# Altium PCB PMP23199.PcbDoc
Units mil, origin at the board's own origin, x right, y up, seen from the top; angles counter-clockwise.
Board outline 2600 x 2075 mil, 2 copper layers (Top Layer, Bottom Layer), stack 62 mil thick; 35 components, 17 nets, 75 pads, 7 vias.
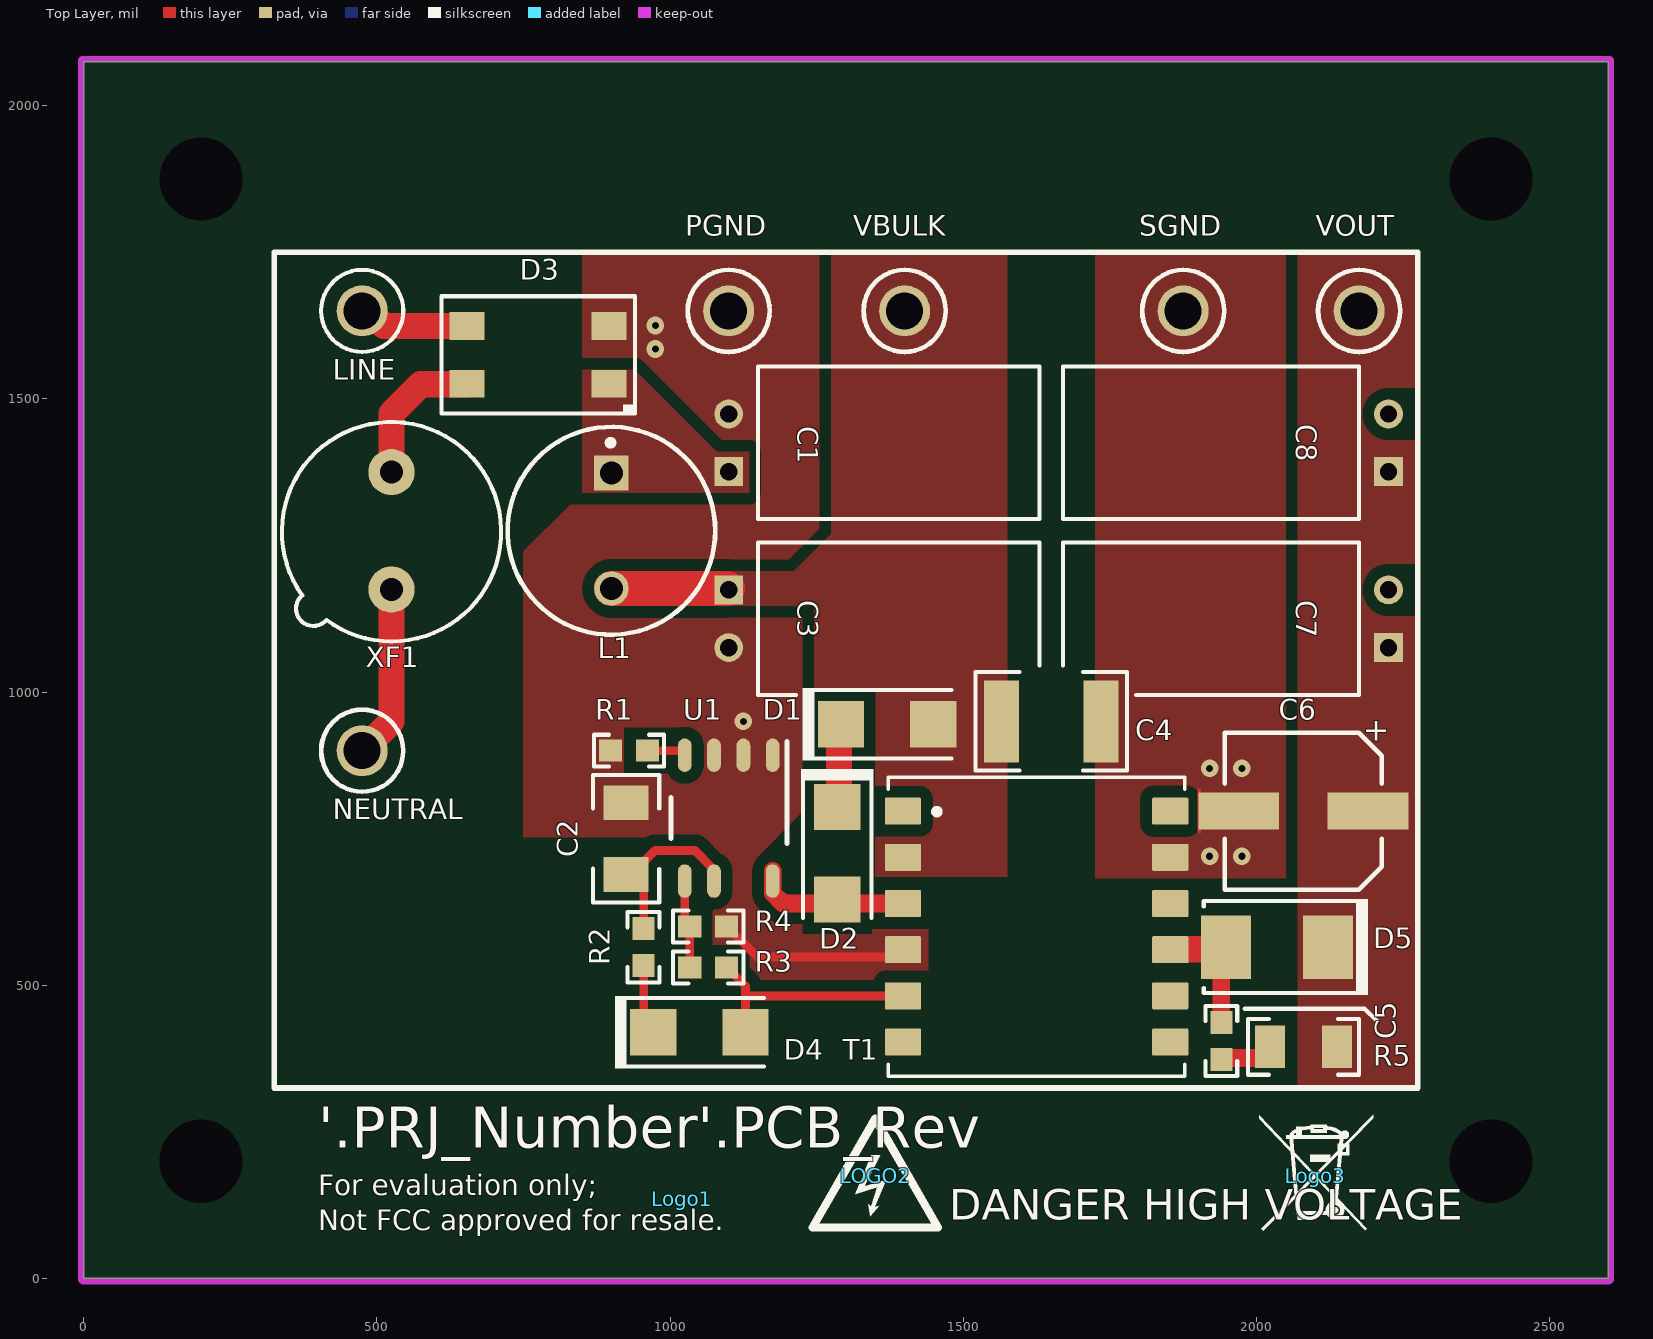
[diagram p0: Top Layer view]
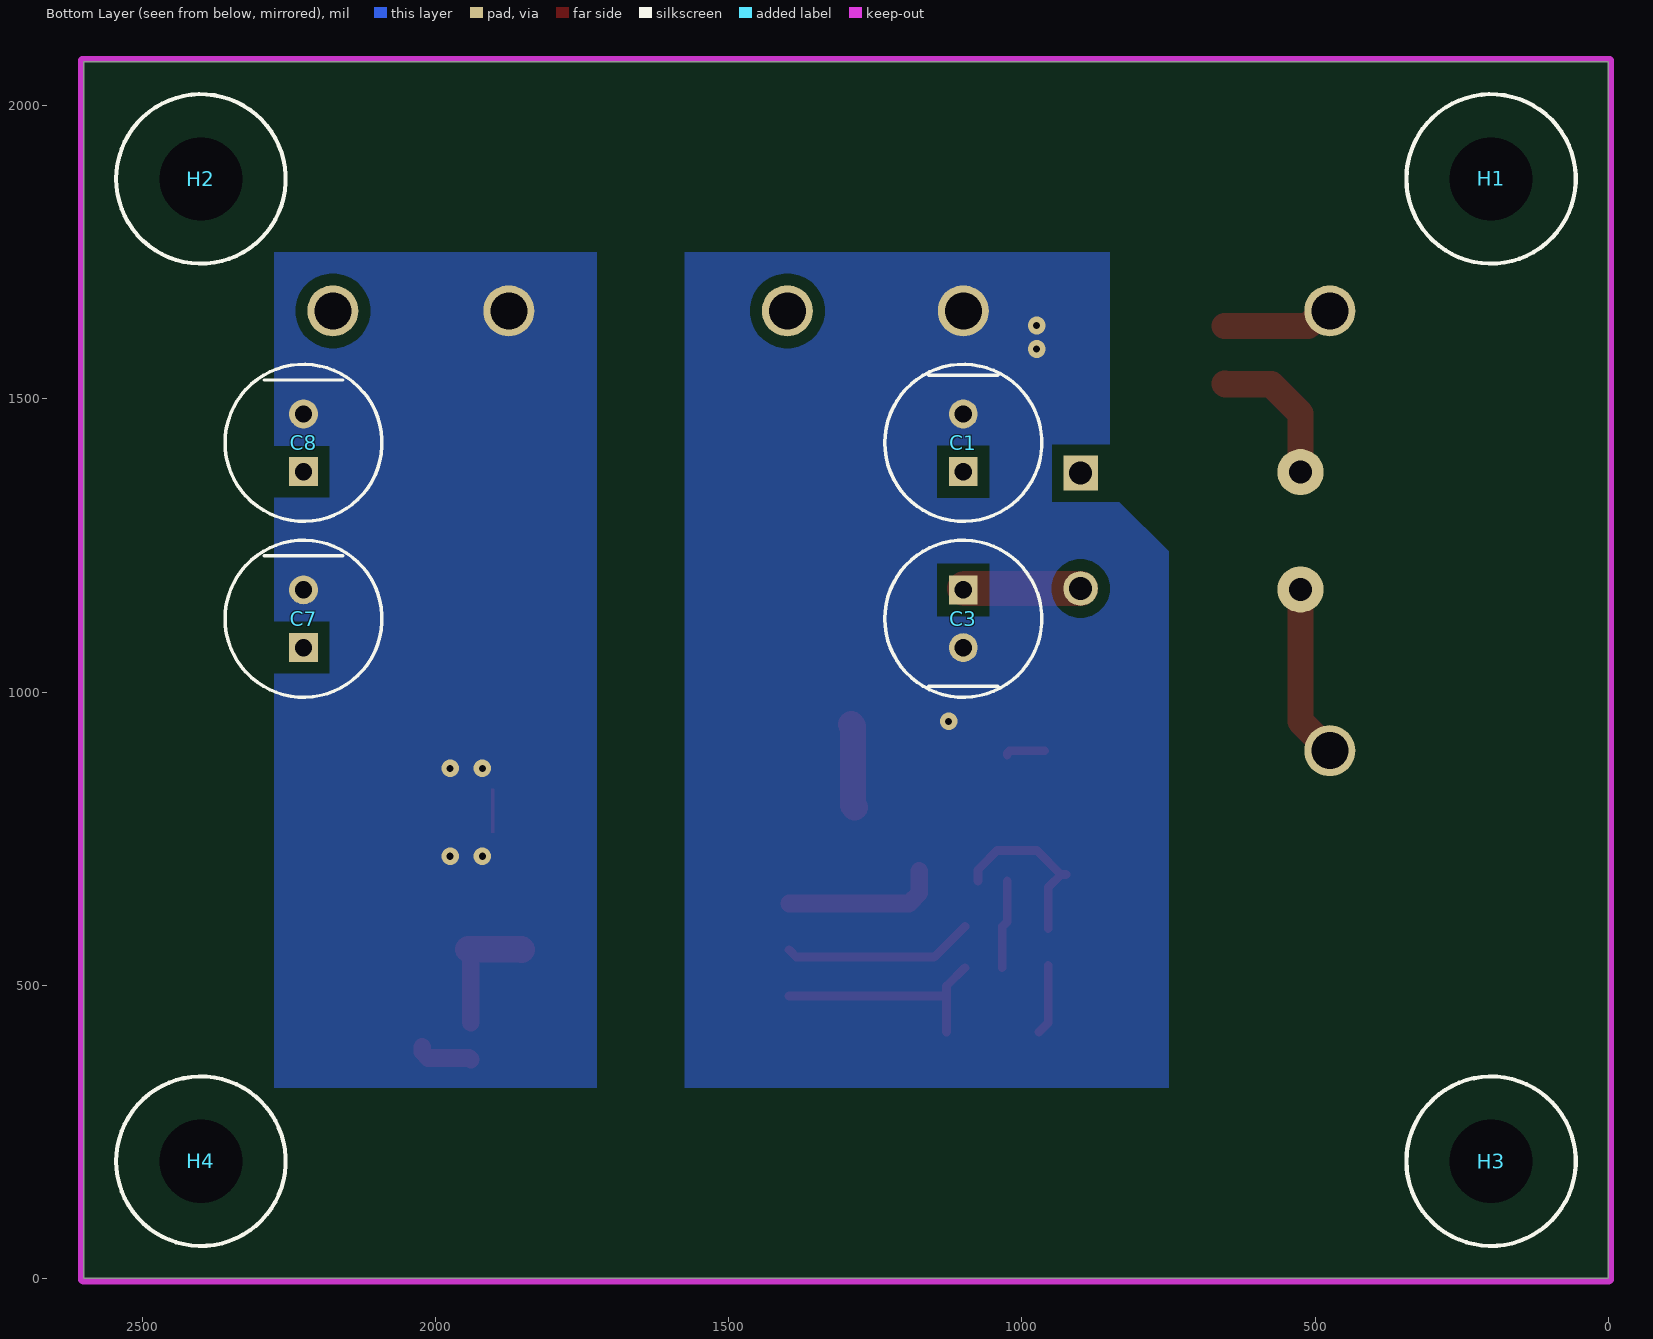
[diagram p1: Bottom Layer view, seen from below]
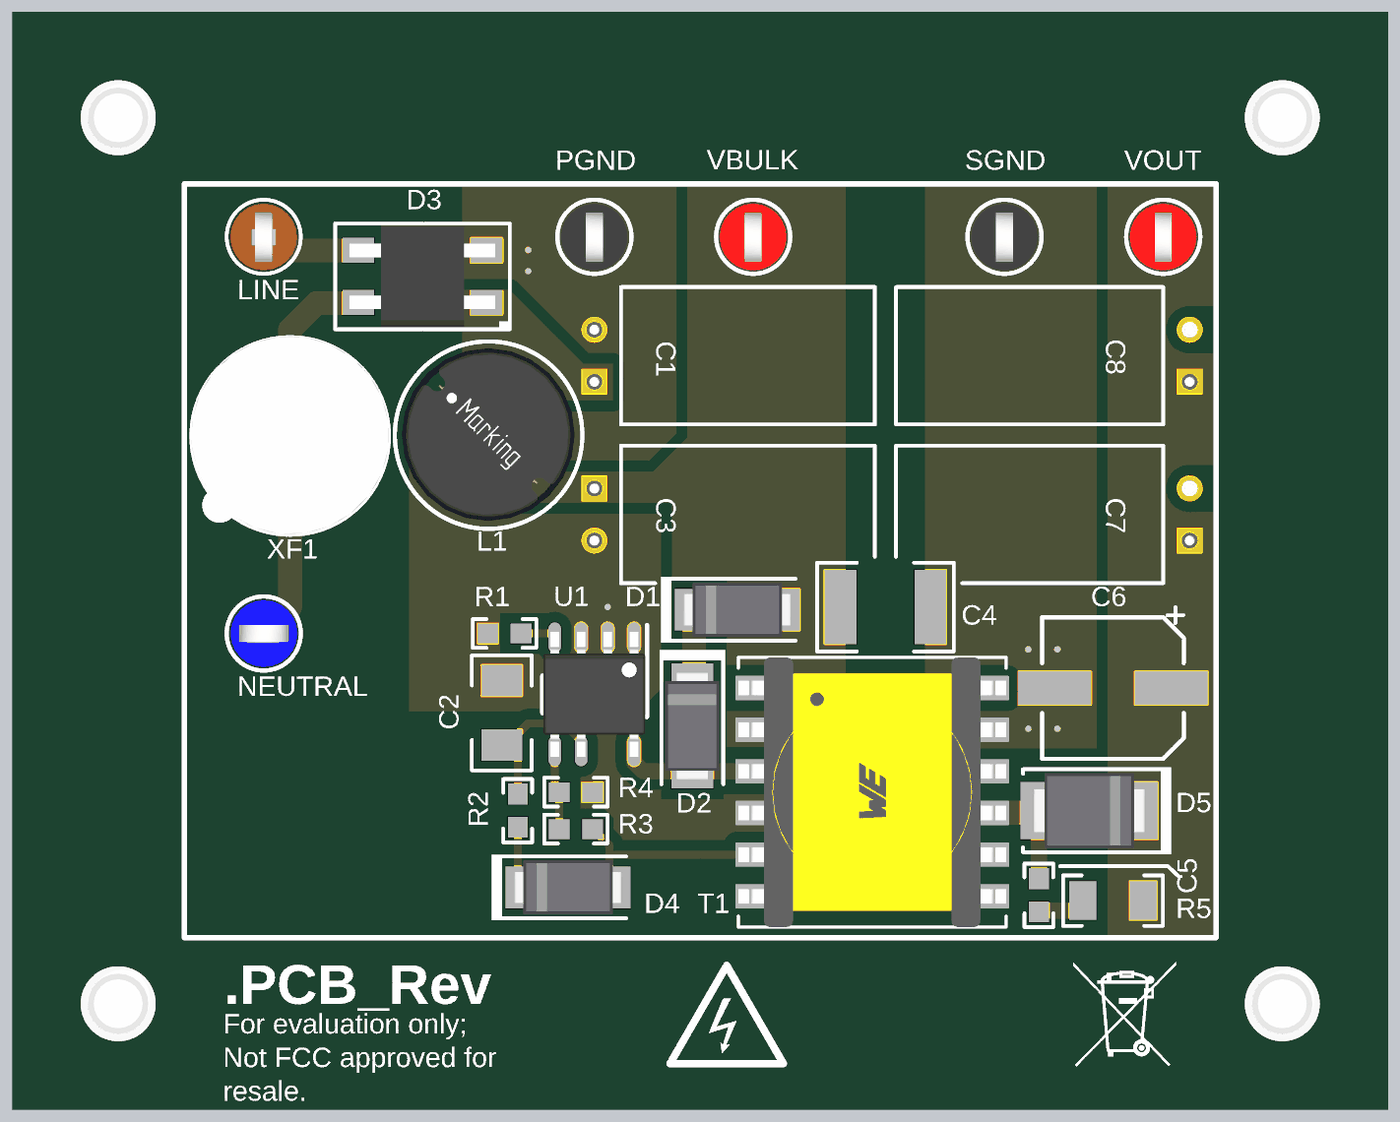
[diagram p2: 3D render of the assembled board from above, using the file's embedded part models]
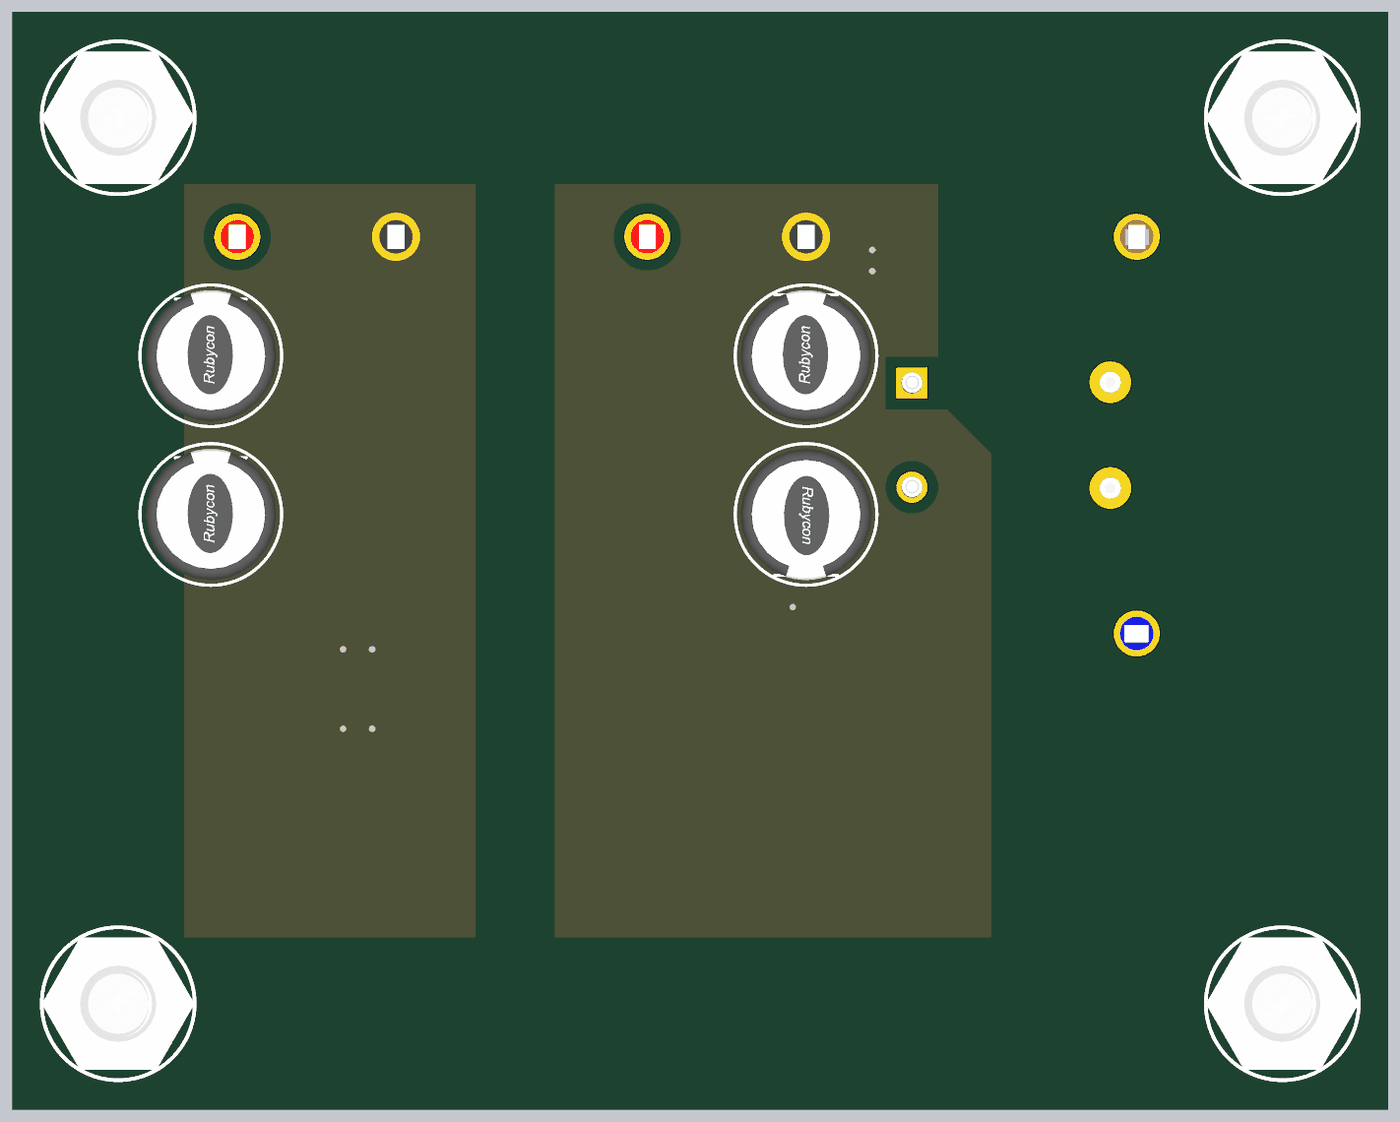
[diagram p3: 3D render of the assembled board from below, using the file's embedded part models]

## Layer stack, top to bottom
Top Solder: solder mask 0.4, Solder Resist, Dk 3.5
Top Layer: signal copper 1.4
Dielectric1: core 59.2, FR-4 High Tg, Dk 4.8
Bottom Layer: signal copper 1.4
Bottom Solder: solder mask 0.4, Solder Resist, Dk 3.5

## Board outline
0,0 0,2075 2600,2075 2600,0

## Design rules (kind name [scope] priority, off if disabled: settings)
AcuteAngle [All] p1: minimum=4.50000000000000E+0001 checktracksonly=FALSE
AssemblyTestPointUsage [All] p1: valid=2
BoardOutlineClearance BoardOutlineClearance_MountingHoles [OnCopper and InComponentClass('Mounting Holes')] p1: gap=25 ignorepadtopadclearanceinfootprint=FALSE
BoardOutlineClearance BoardOutlineClearance_Poly [OnCopper and InPoly] p2: gap=25 ignorepadtopadclearanceinfootprint=FALSE
BoardOutlineClearance [OnCopper and Not InComponentClass('Logo') and not InComponentClass('FiducialMark') and not InRegion(1000,500,4000,800)] p3: gap=25 ignorepadtopadclearanceinfootprint=FALSE
Clearance Clearance_2 [InNetClass('HV') vs Not InNetClass('HV')] p1: gap=60 ignorepadtopadclearanceinfootprint=FALSE
Clearance Clearance_1 [InNetClass('MV') vs Not InNetClass('MV')] p2: gap=30 ignorepadtopadclearanceinfootprint=FALSE
Clearance Clearance_Keepouts [((IsTrack Or IsArc) And Not InPoly) And IsFree and IsKeepOut vs ((IsTrack Or IsArc) And Not InPoly) And IsFree and IsKeepOut] p3: gap=0 ignorepadtopadclearanceinfootprint=FALSE
Clearance Clearance_BoardEdge_MountingHoles [OnCopper and InComponentClass('Mounting Holes') vs IsKeepOut] p4: gap=40 ignorepadtopadclearanceinfootprint=FALSE except(0: Arc-Hole Track-Hole SMDPad-Hole THPad-Hole Via-Hole Fill-Hole Poly-Hole Region-Hole Text-Hole)
Clearance Clearance_BoardEdge_Poly [OnCopper and InPoly vs IsKeepOut] p5: gap=50 ignorepadtopadclearanceinfootprint=FALSE except(0: Arc-Hole Track-Hole SMDPad-Hole THPad-Hole Via-Hole Fill-Hole Poly-Hole Region-Hole Text-Hole)
Clearance Clearance_BoardEdge [OnCopper and Not InComponentClass('Logo') and not InComponentClass('FiducialMark') and not InRegion(1000,500,4000,800) and Not IsKeepout vs IsKeepOut] p6: gap=50 ignorepadtopadclearanceinfootprint=FALSE
Clearance Clearance_Poly [InPolygon] p7: gap=20 ignorepadtopadclearanceinfootprint=FALSE except(0: Arc-Hole Track-Hole SMDPad-Hole THPad-Hole Via-Hole Fill-Hole Poly-Hole Region-Hole Text-Hole)
Clearance [All] p8: gap=7.87 ignorepadtopadclearanceinfootprint=FALSE except(0: Arc-Hole Track-Hole SMDPad-Hole THPad-Hole Via-Hole Fill-Hole Poly-Hole Region-Hole Text-Hole)
ComponentClearance ComponentClearance_MountingHoles_FiducialMarks [InComponentClass('Mounting Holes') vs InComponentClass('FiducialMark')] p1: gap=20 collisioncheckmode=3 verticalgap=10 showdistances=FALSE
ComponentClearance ComponentClearance_Shunt [InComponentClass('Header') vs InComponentClass('Shunt')] p2: gap=0 collisioncheckmode=3 verticalgap=0 showdistances=FALSE
ComponentClearance ComponentClearance_Logo [InComponentClass('Logo')] p3: gap=5 collisioncheckmode=3 verticalgap=10 showdistances=FALSE
ComponentClearance ComponentClearance_ScrewToNut [(HasFootprint('NY PMS 440 0025 PH')) vs (HasFootprint('Keystone_1902C'))] p4: gap=20 collisioncheckmode=3 verticalgap=100000 showdistances=FALSE
ComponentClearance ComponentClearance_MountingHoles [InComponentClass('Mounting Holes')] p5: gap=20 collisioncheckmode=3 verticalgap=10 showdistances=FALSE
ComponentClearance ComponentClearance_SmallPassives [HasFootprint('0201*') or HasFootprint('0402*') or HasFootprint('0508') or HasFootprint('0603*') or HasFootprint('0612') or HasFootprint('0805*') or HasFootprint('0815*') or HasFootprint('0830*') or HasFootprint('1206*') or HasFootprint('1210*') or HasFootprint('1808*') or HasFootprint('1812*') or HasFootprint('1825*') or HasFootprint('2010*') or HasFootprint('2220*') or HasFootprint('2225*') or HasFootprint('2512*') or HasFootprint('2728*') or HasFootprint('3518*') vs HasFootprint('0201*') or HasFootprint('0402*') or HasFootprint('0508') or HasFootprint('0603*') or HasFootprint('0612') or HasFootprint('0805*') or HasFootprint('0815*') or HasFootprint('0830*') or HasFootprint('1206*') or HasFootprint('1210*') or HasFootprint('1808*') or HasFootprint('1812*') or HasFootprint('1825*') or HasFootprint('2010*') or HasFootprint('2220*') or HasFootprint('2225*') or HasFootprint('2512*') or HasFootprint('2728*') or HasFootprint('3518*')] p6: gap=20 collisioncheckmode=3 verticalgap=20 showdistances=FALSE
ComponentClearance ComponentClearance_THtoSMT [IsThruComponent vs IsSMTComponent] p7: gap=10 collisioncheckmode=3 verticalgap=10 showdistances=FALSE
ComponentClearance ComponentClearance_THtoTH [IsThruComponent vs IsThruComponent] p8: gap=10 collisioncheckmode=3 verticalgap=10 showdistances=FALSE
ComponentClearance [All] p9: gap=10 collisioncheckmode=3 verticalgap=10 showdistances=FALSE
DiffPairsRouting [All] p1: maxlimit=100 minlimit=10 mostfreqgap=10 toplayer_minwidth=15 toplayer_maxwidth=15 toplayer_prefwidth=15 bottomlayer_minwidth=15 bottomlayer_maxwidth=15 bottomlayer_prefwidth=15 maxuncoupledlength=1000
FabricationTestPointUsage TestPointUsage [All] p1: valid=2 allowmultiple=FALSE
FabricationTestpoint Testpoint [All] p1: side=3 testpointundercomponent=TRUE minsize=40 maxsize=100 preferedsize=60 minholesize=0 maxholesize=40 preferedholesize=32 testpointgrid=1 allowsidetop=TRUE allowsidebottom=TRUE usegrid=TRUE gridtolerance=0.01
FanoutControl Fanout_LCC [IsLCC] p1: bgadir=Out bgaviamode=Centered fanoutstyle=Auto fanoutdirection=Alternating viagrid=1 // Fanout_LCC (Default Rule)
FanoutControl Fanout_BGA [IsBGA] p2: bgadir=Out bgaviamode=Centered fanoutstyle=Auto fanoutdirection=Alternating viagrid=1 // Fanout_BGA (Default Rule)
FanoutControl Fanout_Default [All] p4: bgadir=Out bgaviamode=Centered fanoutstyle=Auto fanoutdirection=Alternating viagrid=1 // Fanout_Default (Default Rule)
FanoutControl Fanout_Small [(CompPinCount < 5)] p5: bgadir=Out bgaviamode=Centered fanoutstyle=Auto fanoutdirection=OutThenIn viagrid=1 // Fanout_Small (Default Rule)
Height [All] p1: minheight=0 maxheight=3000 prefheight=500
HoleSize [All] p1: absolutevalues=TRUE maxlimit=251 minlimit=7.87 maxpercent=80.000 minpercent=20.000
MinimumAnnularRing MinimumAnnularRing_ThermalPadVias [IsVia and InAnyComponent] p1: minimumring=5.91
MinimumAnnularRing [All] p2: minimumring=8
MinimumSolderMaskSliver MinimumSolderMaskSliver_Logo [InComponentClass('Logo') vs InComponentClass('Logo')] p1: minsoldermaskwidth=0.7
MinimumSolderMaskSliver [All] p2: minsoldermaskwidth=3.94
PlaneConnect [All] p1: planeconnectstyle=Direct reliefexpansion=10 reliefentries=4 reliefconductorwidth=10 reliefairgap=10
PolygonConnect PolygonConnect_15 [All vs IsNamedPolygon('C109_2') Or  IsNamedPolygon('C107_2') Or  IsNamedPolygon('HV') Or  IsNamedPolygon('Q203_5') Or  IsNamedPolygon('C107_2') Or  IsNamedPolygon('HS') Or  IsNamedPolygon('Q201_5') Or  IsNamedPolygon('Q203_5') Or  IsNamedPolygon('C106_2') Or  IsNamedPolygon('C108_2') Or  IsNamedPolygon('Vout') Or  IsNamedPolygon('Q203_5') Or  IsNamedPolygon('C108_2') Or  IsNamedPolygon('C113_2') Or  IsNamedPolygon('Q203_5') Or  IsNamedPolygon('Q201_5') Or  IsNamedPolygon('C107_2') Or  IsNamedPolygon('C102_1') Or  IsNamedPolygon('SGND') Or  IsNamedPolygon('GND') Or  IsNamedPolygon('SGND') Or  IsNamedPolygon('GND') Or  IsNamedPolygon('IN+') Or  IsNamedPolygon('IN+') Or  IsNamedPolygon('Q201_5') Or  IsNamedPolygon('Q201_5') Or  IsNamedPolygon('SGND') Or  IsNamedPolygon('SGND') Or  IsNamedPolygon('Vout') Or  IsNamedPolygon('Vout') Or  IsNamedPolygon('IN+') Or  IsNamedPolygon('GND') Or  IsNamedPolygon('IN+') Or  IsNamedPolygon('GND')] p1: connectstyle=Direct reliefconductorwidth=10 reliefentries=4 polygonreliefangle="90 Angle" airgapwidth=10
PolygonConnect PolygonConnect_14 [All vs IsNamedPolygon('C106_2') Or  IsNamedPolygon('C107_2') Or  IsNamedPolygon('C107_2') Or  IsNamedPolygon('C107_2') Or  IsNamedPolygon('C102_1') Or  IsNamedPolygon('Q203_5') Or  IsNamedPolygon('Vout') Or  IsNamedPolygon('Q203_5') Or  IsNamedPolygon('Q203_5') Or  IsNamedPolygon('Q201_5') Or  IsNamedPolygon('C108_2') Or  IsNamedPolygon('Q203_5') Or  IsNamedPolygon('HS') Or  IsNamedPolygon('HV') Or  IsNamedPolygon('C108_2') Or  IsNamedPolygon('Q201_5') Or  IsNamedPolygon('C109_2') Or  IsNamedPolygon('Q201_5') Or  IsNamedPolygon('Q201_5') Or  IsNamedPolygon('C113_2')] p2: connectstyle=Direct reliefconductorwidth=10 reliefentries=4 polygonreliefangle="90 Angle" airgapwidth=10
PolygonConnect PolygonConnect_13 [All vs IsNamedPolygon('C102_1') Or  IsNamedPolygon('HV') Or  IsNamedPolygon('C107_2') Or  IsNamedPolygon('C109_2') Or  IsNamedPolygon('C107_2') Or  IsNamedPolygon('C108_2') Or  IsNamedPolygon('C106_2') Or  IsNamedPolygon('C108_2') Or  IsNamedPolygon('C113_2') Or  IsNamedPolygon('C107_2')] p3: connectstyle=Direct reliefconductorwidth=10 reliefentries=4 polygonreliefangle="90 Angle" airgapwidth=10
PolygonConnect PolygonConnect_12 [All vs IsNamedPolygon('C107_2') Or  IsNamedPolygon('C113_2') Or  IsNamedPolygon('C106_2') Or  IsNamedPolygon('C107_2') Or  IsNamedPolygon('C107_2') Or  IsNamedPolygon('C102_1')] p4: connectstyle=Direct reliefconductorwidth=10 reliefentries=4 polygonreliefangle="90 Angle" airgapwidth=10
PolygonConnect PolygonConnect_11 [All vs IsNamedPolygon('C106_2') Or  IsNamedPolygon('C102_1') Or  IsNamedPolygon('C107_2') Or  IsNamedPolygon('C107_2') Or  IsNamedPolygon('C107_2')] p5: connectstyle=Direct reliefconductorwidth=10 reliefentries=4 polygonreliefangle="90 Angle" airgapwidth=10
PolygonConnect PolygonConnect_10 [All vs IsNamedPolygon('C106_2')] p6: connectstyle=Direct reliefconductorwidth=10 reliefentries=4 polygonreliefangle="90 Angle" airgapwidth=10
PolygonConnect PolygonConnect_9 [All vs IsNamedPolygon('C11_1') Or  IsNamedPolygon('Vin') Or  IsNamedPolygon('Vin') Or  IsNamedPolygon('5V') Or  IsNamedPolygon('D6_2') Or  IsNamedPolygon('Q3_3') Or  IsNamedPolygon('GND2') Or  IsNamedPolygon('GND2') Or  IsNamedPolygon('GND') Or  IsNamedPolygon('Q3_4') Or  IsNamedPolygon('12V5') Or  IsNamedPolygon('GND') Or  IsNamedPolygon('12V5') Or  IsNamedPolygon('D3_1')] p7: connectstyle=Direct reliefconductorwidth=10 reliefentries=4 polygonreliefangle="90 Angle" airgapwidth=10
PolygonConnect PolygonConnect_8 [All vs IsNamedPolygon('C11_1') Or  IsNamedPolygon('Vin') Or  IsNamedPolygon('12V5') Or  IsNamedPolygon('Q3_3') Or  IsNamedPolygon('GND2') Or  IsNamedPolygon('GND2') Or  IsNamedPolygon('5V') Or  IsNamedPolygon('Q3_4') Or  IsNamedPolygon('12V5')] p8: connectstyle=Direct reliefconductorwidth=10 reliefentries=4 polygonreliefangle="90 Angle" airgapwidth=10
PolygonConnect PolygonConnect_7 [All vs IsNamedPolygon('GND2') Or  IsNamedPolygon('GND2') Or  IsNamedPolygon('5V') Or  IsNamedPolygon('12V5') Or  IsNamedPolygon('12V5') Or  IsNamedPolygon('C11_1')] p9: connectstyle=Direct reliefconductorwidth=10 reliefentries=4 polygonreliefangle="90 Angle" airgapwidth=10
PolygonConnect PolygonConnect_6 [All vs IsNamedPolygon('GND2') Or  IsNamedPolygon('SGND') Or  IsNamedPolygon('GND1') Or  IsNamedPolygon('C901_1') Or  IsNamedPolygon('SGND') Or  IsNamedPolygon('GND2') Or  IsNamedPolygon('GND1')] p10: connectstyle=Direct reliefconductorwidth=10 reliefentries=4 polygonreliefangle="90 Angle" airgapwidth=10
PolygonConnect PolygonConnect_5 [All vs IsNamedPolygon('GND1') Or  IsNamedPolygon('GND1')] p11: connectstyle=Direct reliefconductorwidth=10 reliefentries=4 polygonreliefangle="90 Angle" airgapwidth=10
PolygonConnect PolygonConnect_4 [All vs IsNamedPolygon('C21_1') Or  IsNamedPolygon('C5_1') Or  IsNamedPolygon('C12_2') Or  IsNamedPolygon('C2_2') Or  IsNamedPolygon('C13_1') Or  IsNamedPolygon('C28_1') Or  IsNamedPolygon('C6_1') Or  IsNamedPolygon('GND') Or  IsNamedPolygon('GND2') Or  IsNamedPolygon('C14_1') Or  IsNamedPolygon('C13_1') Or  IsNamedPolygon('Q1_3') Or  IsNamedPolygon('C14_1') Or  IsNamedPolygon('C5_1') Or  IsNamedPolygon('GND2') Or  IsNamedPolygon('C28_1') Or  IsNamedPolygon('D5_2') Or  IsNamedPolygon('D6_2') Or  IsNamedPolygon('D2_1') Or  IsNamedPolygon('C12_2') Or  IsNamedPolygon('D2_1') Or  IsNamedPolygon('C4_1') Or  IsNamedPolygon('C4_1') Or  IsNamedPolygon('C2_2') Or  IsNamedPolygon('GND') Or  IsNamedPolygon('C33_1') Or  IsNamedPolygon('C9_1')] p12: connectstyle=Direct reliefconductorwidth=10 reliefentries=4 polygonreliefangle="90 Angle" airgapwidth=10
PolygonConnect PolygonConnect_3 [All vs IsNamedPolygon('C28_1') Or  IsNamedPolygon('C12_2') Or  IsNamedPolygon('C28_1') Or  IsNamedPolygon('C9_1') Or  IsNamedPolygon('D5_2') Or  IsNamedPolygon('C12_2') Or  IsNamedPolygon('C2_2') Or  IsNamedPolygon('C14_1') Or  IsNamedPolygon('C4_1') Or  IsNamedPolygon('C14_1') Or  IsNamedPolygon('D6_2') Or  IsNamedPolygon('GND2') Or  IsNamedPolygon('Q1_3') Or  IsNamedPolygon('C5_1') Or  IsNamedPolygon('D2_1') Or  IsNamedPolygon('C4_1') Or  IsNamedPolygon('C13_1') Or  IsNamedPolygon('C5_1') Or  IsNamedPolygon('C13_1') Or  IsNamedPolygon('C33_1') Or  IsNamedPolygon('D2_1') Or  IsNamedPolygon('GND') Or  IsNamedPolygon('GND') Or  IsNamedPolygon('GND2') Or  IsNamedPolygon('C2_2') Or  IsNamedPolygon('C6_1') Or  IsNamedPolygon('C21_1')] p13: connectstyle=Direct reliefconductorwidth=10 reliefentries=4 polygonreliefangle="90 Angle" airgapwidth=10
PolygonConnect PolygonConnect_2 [All vs IsNamedPolygon('C21_1') Or  IsNamedPolygon('C4_1') Or  IsNamedPolygon('D5_2') Or  IsNamedPolygon('C5_1') Or  IsNamedPolygon('C14_1') Or  IsNamedPolygon('C13_1') Or  IsNamedPolygon('C4_1') Or  IsNamedPolygon('C33_1') Or  IsNamedPolygon('C12_2') Or  IsNamedPolygon('D2_1') Or  IsNamedPolygon('C2_2') Or  IsNamedPolygon('C28_1') Or  IsNamedPolygon('C12_2') Or  IsNamedPolygon('D2_1') Or  IsNamedPolygon('C5_1') Or  IsNamedPolygon('Q1_3') Or  IsNamedPolygon('GND') Or  IsNamedPolygon('D6_2') Or  IsNamedPolygon('C6_1') Or  IsNamedPolygon('C2_2') Or  IsNamedPolygon('C14_1') Or  IsNamedPolygon('C28_1') Or  IsNamedPolygon('C13_1') Or  IsNamedPolygon('C9_1') Or  IsNamedPolygon('GND')] p14: connectstyle=Direct reliefconductorwidth=10 reliefentries=4 polygonreliefangle="90 Angle" airgapwidth=10
PolygonConnect PolygonConnect_1 [All vs IsNamedPolygon('C28_1') Or  IsNamedPolygon('D5_2') Or  IsNamedPolygon('C5_1') Or  IsNamedPolygon('C5_1') Or  IsNamedPolygon('D2_1') Or  IsNamedPolygon('C21_1') Or  IsNamedPolygon('C9_1') Or  IsNamedPolygon('C4_1') Or  IsNamedPolygon('C14_1') Or  IsNamedPolygon('C28_1') Or  IsNamedPolygon('C6_1') Or  IsNamedPolygon('C12_2') Or  IsNamedPolygon('C33_1') Or  IsNamedPolygon('C4_1') Or  IsNamedPolygon('C13_1') Or  IsNamedPolygon('C12_2') Or  IsNamedPolygon('D6_2') Or  IsNamedPolygon('C2_2') Or  IsNamedPolygon('C14_1') Or  IsNamedPolygon('D2_1') Or  IsNamedPolygon('C2_2') Or  IsNamedPolygon('C13_1')] p15: connectstyle=Direct reliefconductorwidth=10 reliefentries=4 polygonreliefangle="90 Angle" airgapwidth=10
PolygonConnect [All] p16: connectstyle=Direct reliefconductorwidth=10 reliefentries=4 polygonreliefangle="90 Angle" airgapwidth=10
RoutingVias ThermalPadVias [IsVia and InAnyComponent] p1: holewidth=7.87 width=19.68 viastyle="Through Hole" minholewidth=7.87 minwidth=19.68 maxholewidth=12.99 maxwidth=23.62
RoutingVias [All] p2: holewidth=16 width=34 viastyle="Through Hole" minholewidth=7.87 minwidth=20 maxholewidth=40 maxwidth=65
SilkToBoardRegionClearance [Not ((IsComment or IsDesignator) And (Hide <> 'False')) and not InRegion(1000,500,4000,800)] p1:
SilkToSilkClearance SilkToSilkClearance_Pb-FreeLogo [(HasFootprint('Pb-Free_Overlay_Medium') OR HasFootprint('Pb-Free_Overlay_Small')) vs (HasFootprint('Pb-Free_Overlay_Medium') OR HasFootprint('Pb-Free_Overlay_Small'))] p1: silktosilkclearance=0
SilkToSilkClearance [All] p2: silktosilkclearance=4
SilkToSolderMaskClearance SilkToComponentPadClearance [IsPad and InAnycomponent] p1: minsilkscreentomaskgap=5 clearancetoexposedcopper=TRUE
SilkToSolderMaskClearance "Silk to Solder Mask Opening" [All] p2: minsilkscreentomaskgap=4 clearancetoexposedcopper=FALSE
SolderMaskExpansion [All] p1: expansion=1.97 istentingtop=FALSE
Width [All] p1: maxlimit=100 minlimit=6 preferedwidth=10 checkconnectedcopper=TRUE
14 further rules are at their usual default settings.

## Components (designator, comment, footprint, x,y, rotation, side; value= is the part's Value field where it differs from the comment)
C1 "250PX2R2MEFC6.3X11" FP-250PX2R2MEFC6.3X11_RADIAL-MFG 1100,1425 r270 bottom value=2.2µF
C2 "GRM31CR71E106KA12L" 1206_180M 925,750 r90 top value=10uF
C3 "250PX2R2MEFC6.3X11" FP-250PX2R2MEFC6.3X11_RADIAL-MFG 1100,1125 r90 bottom value=2.2µF
C4 "C4532X7R3D222K130KA" 1812_HV 1650,950 r180 top value=2200pF
C5 "GRM188R71H471KA01D" 0603 1940,405 r90 top value=470pF
C6 "875105344009" WCAP-PSLP_630x580 2080,796.85 r180 top value=82uF
C7 "6.3ZLH470MEFC6.3X11" FP-6.3ZLH470MEFC6.3X11_RADIAL-MFG 2225,1125 r270 bottom value=470µF
C8 "6.3ZLH470MEFC6.3X11" FP-6.3ZLH470MEFC6.3X11_RADIAL-MFG 2225,1425 r270 bottom value=470µF
D1 "SMAJ170A" SMA 1370,945 r0 top value=170V
D2 "US1G-13-F" SMA 1285,725 r270 top value=400V
D3 "RH06-T" MiniDIP 775,1575 r180 top value=600V
D4 "US1B-13-F" SMA 1050,420 r0 top value=100V
D5 "B160B-13-F" SMB 2035,565 r180 top value=60V
H1 "4820" KEYSTONE_4820 200,1875 r180 bottom
H2 "4820" KEYSTONE_4820 2400,1875 r180 bottom
H3 "4820" KEYSTONE_4820 200,200 r180 bottom
H4 "4820" KEYSTONE_4820 2400,200 r180 bottom
L1 "744741101" WE-TI_8055 900,1275 r270 top value=100uH
LINE "5125" Keystone5125 475,1650 r0 top
Logo1 "FCC disclaimer" FCC_disclaimer 1020,135 r0 top
LOGO2 "DANGER HIGH VOLTAGE" IEC_HighVoltage_Small 1350,175 r0 top
Logo3 "WEEE logo" WEEE_Minimum 2100,175 r0 top
NEUTRAL "5127" Keystone5127 475,900 r90 top
PGND "5011" Keystone5011 1100,1650 r0 top
R1 "CRCW06033K01FKEA" 0603 930,900 r0 top value=3.01k
R2 "CRCW060310R0JNEA" 0603 955,565 r90 top value=10
R3 "CRCW060395K3FKEA" 0603 1065,530 r0 top value=95.3k
R4 "CRCW060332K4FKEA" 0603 1065,600 r180 top value=32.4k
R5 "CRCW120610K0JNEA" 1206 2080,395 r0 top value=10k
SGND "5011" Keystone5011 1875,1650 r0 top
T1 "750319943" FP-750319943_SMT12_12MM85_12MM95-MFG 1625,600 r0 top
U1 "UCC28911DR" D0007A_N 1100,785 r270 top
VBULK "5010" Keystone5010 1400,1650 r0 top
VOUT "5010" Keystone5010 2175,1650 r0 top
XF1 "56000001009" FuseHolder_560000010 525,1275 r270 top value=TR5

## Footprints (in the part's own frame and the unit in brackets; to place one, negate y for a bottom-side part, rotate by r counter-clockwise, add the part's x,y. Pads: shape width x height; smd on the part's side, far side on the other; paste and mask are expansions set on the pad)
0603 [mm] "0603 from SM-752 data"
  rect 1x0.95 smd: 1(-0.8,0) 2(0.8,0)
  silkscreen extent -1.52,-0.69 1.52,0.69, body extent -0.87,-0.47 0.87,0.47, height 1
1206 [mm] "1206 from SM-752 data"
  rect 1.3x1.85 smd: 1(-1.45,0) 2(1.45,0)
  silkscreen extent -2.4,-1.21 2.4,1.21, body extent -1.7,-0.9 1.7,0.9, height 1.35
1206_180M [mm] "1206_180"
  rect 1.5x1.95 smd: 1(-1.55,0) 2(1.55,0)
  silkscreen extent -2.76,-1.44 2.76,1.44, body extent -1.75,-0.95 1.75,0.95, height 1.8
1812_HV [mil] "PRG recommended land pattern"
  rect 60x140 smd: 1(-85,0) 2(85,0)
  silkscreen extent -129,-84 129,84, body extent -94,-67 94,67, height 53
D0007A_N [mm] "SOIC, 7-Leads, Body 4.9x3.9mm, Pitch 1.27mm, IPC Medium Density"
  oval 1.45x0.6 smd: 1(-2.725,1.905) 2(-2.725,0.635) 3(-2.725,-0.635) 4(-2.725,-1.905) 5(2.725,-1.905) 6(2.725,-0.635) 8(2.725,1.905)
  silkscreen extent -3.32,-2.5 1.1,2.52, body extent -3.01,-2.45 3.01,2.45, height 1.75
FCC_disclaimer [mil]
FP-6.3ZLH470MEFC6.3X11_RADIAL-MFG [mm]
  round 1.25 hole 0.75 paste-1000 mask+0: 1(-1.25,0)
  rect 1.25x1.25 hole 0.75 paste-1000 mask+0: 2(1.25,0)
  silkscreen extent -3.4,-3.4 3.4,3.4, body extent -3.15,-3.15 3.15,3.15, height 12.5
FP-250PX2R2MEFC6.3X11_RADIAL-MFG [mm]
  round 1.25 hole 0.75 paste-1000 mask+0: 1(-1.25,0)
  rect 1.25x1.25 hole 0.75 paste-1000 mask+0: 2(1.25,0)
  silkscreen extent -3.4,-3.4 3.4,3.4, body extent -3.15,-3.15 3.15,3.15, height 13
FP-750319943_SMT12_12MM85_12MM95-MFG [mm]
  rrect9% 1.57x1.17 smd paste+0 mask+0: 1(-5.79,5) 2(-5.79,3) 3(-5.79,1) 4(-5.79,-1) 5(-5.79,-3) 6(-5.79,-5) 7(5.79,-5) 8(5.79,-3) 9(5.79,-1) 10(5.79,1) 11(5.79,3) 12(5.79,5)
  silkscreen extent -6.43,-6.48 6.43,6.48, body extent -6.68,-6.58 6.68,6.58, height 0.25
FuseHolder_560000010 [mm] "Littelfuse fuse holder TR5"
  round 2 hole 1: 1(-2.54,0) 2(2.54,0)
  silkscreen extent -4.71,-4.75 4.79,4.75, body extent -4.75,-4.74 4.75,4.75, height 5.6
IEC_HighVoltage_Small [mil]
  silkscreen extent -107,-88 107,97
Keystone5010 [mil] "Keystone Multipurpose loops"
  round 87 hole 63: 1(0,0)
  silkscreen extent -70,-70 70,70, body extent -63,-63 63,62, height 319
Keystone5011 [mil] "Keystone Multipurpose loops"
  round 87 hole 63: 1(0,0)
  silkscreen extent -70,-70 70,70, body extent -63,-63 63,62, height 319
Keystone5125 [mil] "Keystone Multipurpose loops"
  round 87 hole 63: 1(0,0)
  silkscreen extent -70,-70 70,70, body extent -63,-63 63,62, height 319
Keystone5127 [mil] "Keystone Multipurpose loops"
  round 87 hole 63: 1(0,0)
  silkscreen extent -70,-70 70,70, body extent -63,-63 63,62, height 319
KEYSTONE_4820 [mm] "HEX NYLON STANDOFF 6-32, M-F 1\""
  round 0.025 on Mech4: 0(0,0)
  round 1 hole 3.6 unplated: MH(0,0)
  silkscreen extent -3.67,-3.67 3.67,3.67, body extent -3.67,-3.17 3.67,3.18, height 25.42
MiniDIP [mm] "Land pattern created based on STEP model."
  rect 1.52x1.2 smd: 1(-3.075,1.25) 2(-3.075,-1.25) 3(3.075,-1.25) 4(3.075,1.25)
  silkscreen extent -4.19,-2.54 4.19,2.54, body extent -3.5,-2.45 3.5,2.45, height 2.75
SMA [mm] "Molded Diode, 2-Leads, Body 4.3x2.6mm, IPC Medium Density, based on OnSemi component dimensions and land pattern"
  rect 2x2 smd: 1(-2,0) 2(2,0)
  silkscreen extent -3.66,-1.57 2.79,1.57, body extent -2.6,-1.3 2.6,1.3, height 2.42
SMB [mil] "Molded Diode, 2-Leads, Body 5.4x3.6mm, IPC Medium Density, based on OnSemi component dimensions"
  rect 85x107.99 smd: 1(-87.01,0) 2(87.01,0)
  silkscreen extent -155,-82 125,82, body extent -106,-71 106,71, height 91
WCAP-PSLP_630x580 [mm] "SMD, 2-Leads, Dia 6.3mm"
  rect 3.5x1.6 smd: 1(-2.8,0) 2(2.8,0)
  silkscreen extent -3.4,-3.4 3.4,3.4, body extent -3.4,-3.4 3.4,3.4, height 5.81
WE-TI_8055 [mm] "Wurth"
  rect 1.5x1.5 hole 1: 1(-2.5,0)
  round 1.5 hole 1: 2(2.5,0)
  silkscreen extent -4.5,-4.5 4.5,4.5, body extent -5.89,-5.88 5.81,5.83, height 5.51
WEEE_Minimum [mil] "WEEElie bin"
  silkscreen extent -95,-94 99,104

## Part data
C1 C3: library part CMP-0094367-1, "2.2 µF 250 V Aluminum Electrolytic Capacitors Radial, Can - 1000 Hrs @ 105°C", Digikey Part Number=1189-1207-ND, Leakage Current=55uA, Manufacturer=Rubycon, Mouser Part Number=232-250PX2R2MEFC63X1, Operating Temperature Range="-40°C to +105°C", Tolerance_%=20%, ValueDisplayed=2.2uF
C2: library part CMP-0008965-2, "CAP, CERM, 10 uF, 25 V, +/- 10%, X7R, 1206", Cap_Case=2220, Manufacturer=MuRata, Supplier Part Number 1=81-GRM31CR71E106KA12, TempCo=X7R, Tolerance_%=10%, Value1=Unknown, Value2=25V, ValueDisplayed=10uF
C4: library part CMP-0009358-2, "CAP, CERM, 2200 pF, 2000 V, +/- 10%, X7R, 1812", Cap_Case=1812, Manufacturer=TDK, Supplier Part Number 1=445-2389-1-ND, TempCo=X7R, Tolerance_%=10%, Value1=Unknown, Value2=2000V, ValueDisplayed=2200pF
C5: library part CMP-0007455-4, "CAP, CERM, 470 pF, 50 V, +/- 10%, X7R, 0603", Cap_Case=0603, Manufacturer=MuRata, Supplier Part Number 1=490-1489-1-ND, TempCo=X7R, Tolerance_%=10%, Value1=Unknown, Value2=50V, ValueDisplayed=470pF
C6: library part CMP-0012165-3, "CAP, Aluminum Polymer, 82 uF, 16 V, +/- 20%, 0.03 ohm, D6.3xL5.8mm SMD", Cap_Case=6.3x5.8mm, Manufacturer="Wurth Elektronik", Supplier Part Number 1=732-6424-1-ND, Tolerance_%=20%, Value1="0.03 ohm", Value2=16V, ValueDisplayed=82uF
C7 C8: library part CMP-0094403-1, "470 µF 6.3 V Aluminum Electrolytic Capacitors Radial, Can - 6000 Hrs @ 105°C", Digikey Part Number=1189-1769-ND, Leakage Current=29.61uA, Manufacturer=Rubycon, Mouser Part Number=232-63ZLH470MEFC63X1, Operating Temperature Range="-40°C to +105°C", Tolerance_%=20%, ValueDisplayed=470uF
D1: library part CMP-0084984-1, "Diode, TVS, Uni, 170 V, 275 Vc, 400 W, 1.5 A, SMA", Manufacturer=Littelfuse, Value1=275V
D2: library part CMP-0077026-2, "Diode, Ultrafast, 400 V, 1 A, SMA", Manufacturer="Diodes Inc.", Value1=1A, Value2=1.3V
D3: library part CMP-0029221-3, "Diode, Switching-Bridge, 600 V, 0.5 A, MiniDIP", Manufacturer="Diodes Inc.", Value1=0.5A, Value2=1.15V
D4: library part CMP-0076888-2, "Diode, Ultrafast, 100 V, 1 A, SMA", Manufacturer="Diodes Inc.", Value1=1A, Value2=1V
D5: library part CMP-0028390-2, "Diode, Schottky, 60 V, 1 A, SMB", Manufacturer="Diodes Inc.", Value1=1A, Value2=0.7V
H1 H2 H3 H4: library part CMP-0003652-1, Manufacturer=Keystone, Supplier Part Number 1=36-4820-ND
L1: library part CMP-0064515-2, "Inductor, Wirewound, Ferrite, 100 uH, 1.1 A, 0.39 ohm, TH", Manufacturer="Wurth Elektronik", Supplier Part Number 1=732-3729-ND, Value1="0.39 ohm", Value2=1.1A, ValueDisplayed=100uH
LINE: library part CMP-0055157-1, "Test Point, Multipurpose, Brown, TH", Color=Brown, Manufacturer=Keystone, Supplier Part Number 1=36-5125-ND
Logo1: library part CMP-0074847-1, "FCC_disclaimer"
LOGO2: library part CMP-0074835-1, "IEC 61010-1 High Voltage Warning"
Logo3: library part CMP-0074769-1
NEUTRAL: library part CMP-0055156-1, "Test Point, Multipurpose, Blue, TH", Color=Blue, Manufacturer=Keystone, Supplier Part Number 1=36-5127-ND
PGND SGND: library part CMP-0055148-1, "Test Point, Multipurpose, Black, TH", Color=Black, Manufacturer=Keystone, Supplier Part Number 1=36-5011-ND
R1: library part CMP-0022371-4, "RES, 3.01 k, 1%, 0.1 W, AEC-Q200 Grade 0, 0603", Manufacturer=Vishay-Dale, Power_W=100mW, Supplier Part Number 1=541-3.01KHCT-ND, TempCo="100 ppm/C", Tolerance_%=1%, Value2=0.1W, Value_Code=3k01, ValueDisplayed=3.01k
R2: library part CMP-0025703-4, "RES, 10, 5%, 0.1 W, AEC-Q200 Grade 0, 0603", Manufacturer=Vishay-Dale, Power_W=100mW, Supplier Part Number 1=541-10GCT-ND, TempCo="200 ppm/C", Tolerance_%=5%, Value2=0.1W, Value_Code=10R0, ValueDisplayed=10
R3: library part CMP-0022659-4, "RES, 95.3 k, 1%, 0.1 W, AEC-Q200 Grade 0, 0603", Manufacturer=Vishay-Dale, Power_W=100mW, Supplier Part Number 1=541-95.3KHCT-ND, TempCo="100 ppm/C", Tolerance_%=1%, Value2=0.1W, Value_Code=95k3, ValueDisplayed=95.3k
R4: library part CMP-0022334-4, "RES, 32.4 k, 1%, 0.1 W, AEC-Q200 Grade 0, 0603", Manufacturer=Vishay-Dale, Power_W=100mW, Supplier Part Number 1=541-32.4KHCT-ND, TempCo="100 ppm/C", Tolerance_%=1%, Value2=0.1W, Value_Code=32k4, ValueDisplayed=32.4k
R5: library part CMP-0018576-3, "RES, 10 k, 5%, 0.25 W, AEC-Q200 Grade 0, 1206", Manufacturer=Vishay-Dale, Power_W=250mW, Supplier Part Number 1=541-10KECT-ND, TempCo="200 ppm/C", Tolerance_%=5%, Value2=0.25W, Value_Code=10k0, ValueDisplayed=10k
T1: library part CMP-0094334-1, "TRANSFORMER", Frequency_Fixed=110kHz, Manufacturer=Wurth, Operating Temperature Range="-40°C to +125°C", Voltage_Isolation_Vrms=1.25kV
U1: library part CMP-0074093-2, "700V Flyback Switcher with Constant-Voltage Constant-Current and Primary-side Regulation, D0007A (SOIC-7)", Alternate Manufacturer="Texas Instruments", Alternate PartNumber=UCC28911D
VBULK VOUT: library part CMP-0055147-1, "Test Point, Multipurpose, Red, TH", Color=Red, Manufacturer=Keystone, Supplier Part Number 1=36-5010-ND
XF1: library part CMP-0003627-1, "Fuse Holder, TR5, TH", Manufacturer=Littelfuse, Supplier Part Number 1=WK6235-ND

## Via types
v1: diameter 30, hole 12, Top Layer to Bottom Layer, tented both sides, 7 vias

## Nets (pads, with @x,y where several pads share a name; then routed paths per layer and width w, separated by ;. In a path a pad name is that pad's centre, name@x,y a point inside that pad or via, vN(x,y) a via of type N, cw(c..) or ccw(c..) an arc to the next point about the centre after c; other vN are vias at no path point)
NetC1_2: C1.2 D3.1 L1.1
NetC5_1: C5.1 R5.1 | length 96.7
  Top Layer w30: C5.1 1942.49,376 2012.32,376 2022.91,386.59 R5.1
NetC5_2: C5.2 D5.2 T1.9 | length 223.2
  Top Layer w30: C5.2 1940,557.01 1944.15,561.16 D5.2
  Top Layer w45: T1.9 1853.48,561.16 D5.2@1944.15,561.16
NetC6_1: C6.1 C7.2 C8.2 D5.1 R5.2 VOUT.1
NetD1_1: D1.1 D2.1 | length 143.9
  Top Layer w45: D2.1 1288.13,806.87 1288.13,941.87 D1.1
NetD2_2: D2.2 T1.3 U1.8 | length 267.4
  Top Layer w30: U1.8@1175,695 1175,656.94 1192.57,639.37 T1.3
NetD3_3: D3.3 LINE.1 | length 189.6
  Top Layer w45: LINE.1 486.37,1650 512.15,1624.21 D3.3
NetD3_4: D3.4 XF1.1 | length 250
  Top Layer w45: XF1.1 525,1475 574.67,1524.67 652.81,1524.67 D3.4
NetD4_1: D4.1 R2.1 | length 120.2
  Top Layer w15: R2.1 955,436.26 D4.1
NetD4_2: D4.2 R3.2 T1.5 | length 393.6
  Top Layer w15: R3.2 1097.48,530 1128.74,498.74 1128.74,478.5 ; D4.2 1128.74,478.5 ; T1.5 1132.13,481.89 1128.74,478.5
NetNEUTRAL_1: NEUTRAL.1 XF1.2 | length 295.7
  Top Layer w45: NEUTRAL.1 525,950 XF1.2
NetR1_2: R1.2 U1.4 | length 68.9
  Top Layer w15: R1.2 1021.02,900 1025,896.02 U1.4
NetR3_1: R3.1 R4.2 U1.5 | length 151.2
  Top Layer w15: U1.5 1025,608.5 R4.2 R3.1
PGND: C1.1 C2.2 C3.1 D3.2 PGND.1 R1.1 R4.1 T1.4 U1.1 U1.2 U1.3 | length 327.3
  Top Layer w15: R4.1 1097.48,600 1149.43,548.05 1384.47,548.05 T1.4
  other v1: 1125,950 975,1585 975,1625
SGND: C4.1 C6.2 C7.1 C8.1 SGND.1 T1.11
  other v1: 1920,720 1975,720 1920,870 1975,870
VBULK: C3.2 C4.2 D1.2 L1.2 T1.2 VBULK.1 | length 197.6
  Top Layer w60: L1.2 C3.2@1097.64,1176.57
VDD: C2.1 R2.2 U1.6 | length 301.5
  Top Layer w15: C2.1 C2.1@932.97,688.98 ; R2.2 955,666.95 C2.1@932.97,688.98 ; U1.6 1075,696.78 1070.69,701.09 1070.69,701.26 1041.95,730 974.88,730 933.86,688.98 C2.1@932.97,688.98
pads on no net: H1.0 H1.MH H2.0 H2.MH H3.0 H3.MH H4.0 H4.MH T1.1 T1.6 T1.7 T1.8 T1.10 T1.12

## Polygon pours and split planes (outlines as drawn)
SGND on Top Layer "TOP_LAYER_SGND_P005" (solid, remove dead copper, pour order 5): 2275,325 2275,1750 1725,1750 1725,325
NetC6_1 on Top Layer "TOP_LAYER_NETC6_1_P004" (solid, remove dead copper, pour order 4): 2275,325 2275,1750 2070,1750 2070,325
PGND on Top Layer "TOP_LAYER_PGND_P002" (solid, remove dead copper, pour order 2): 1575,325 750,325 750,1240 850,1340 850,1750 1575,1750
VBULK on Top Layer "TOP_LAYER_VBULK_P001" (solid, remove dead copper, pour order 1): 1100,1206 1211,1206 1275,1270 1275,1750 1575,1750 1575,685 1350,685 1350,1005 1246.25,1005 1246.25,1147 1100,1147
NetC1_2 on Top Layer "TOP_LAYER_NETC1_2_P000" (solid, remove dead copper, pour order 0): 850,1550 850,1340 1135,1340 1135,1410 1080,1410 940,1550
SGND on Bottom Layer "BOTTOM_LAYER_SGND_P006" (solid, remove dead copper, pour order 6): 2275,325 2275,1750 1725,1750 1725,325
PGND on Bottom Layer "BOTTOM_LAYER_PGND_P003" (solid, remove dead copper, pour order 3): 1575,325 750,325 750,1240 850,1340 850,1750 1575,1750

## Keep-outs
Keep-Out Layer:
  lines w10: -5,0 ccw(c0,0) 0,-5 ; -5,0 ccw(c0,0) 0,-5 ; -5,0 -5,2075 ; -5,2075 cw(c0,2075) 0,2080 ; -5,2075 cw(c0,2075) 0,2080 ; 0,-5 2600,-5 ; 0,2080 2600,2080 ; 2600,-5 ccw(c2600,0) 2605,0 ; 2600,-5 ccw(c2600,0) 2605,0 ; 2600,2080 cw(c2600,2075) 2605,2075 ; 2600,2080 cw(c2600,2075) 2605,2075 ; 2605,0 2605,2075
  text ".Layer_Name" at 577,-858.49 h60

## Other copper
Top Layer:
  pour cut-out: 2225,1218.82 2225,1129.61 2300,1129.61 2300,1518.82 2225,1518.82 2225,1429.61 2285,1429.61 2285,1218.82
  pour cut-out: 2054.27,682.83 2060.11,676.99 1724.8,676.99 1724.8,682.83 1824.12,682.83
  region net SGND: 1900,835 1900,760 1905,760 1905,835
  pour cut-out: 1001.18,938.7 1022.6,938.7 1025,938.7 1025,935 1001.18,935
  pour cut-out: 850,1319.61 826.55,1319.61 825,1321.16 826.14,1322.3 850.29,1322.3
  pour cut-out: 1225.63,863.11 1225.63,1130 1235,1130 1235,863.11
  pour cut-out: 1150.04,719.96 1242.88,812.81 1249.61,812.81 1249.61,805.37 1157.35,713.11
  pour cut-out: 969.88,752.74 736.28,752.74 740.59,748.43 969.8,748.43
  pour cut-out: 1344.37,595.91 1344.37,600 1445,600 1445,520 1425.88,520 1425.88,525.35 1440,525.35 1440,595.91
  pour cut-out: 1368.21,840.31 1368.21,753.39 1343.5,753.39 1343.5,840.31
  text ".Layer_Name" at 577,-858.49 h60
Bottom Layer:
  pour cut-out: 2225,1120.39 2225,1031.18 2300,1031.18 2300,1420.39 2225,1420.39 2225,1331.18 2285,1331.18 2285,1120.39
  pour cut-out: 850.47,1323.9 826.1,1323.9 825,1325 826.35,1326.35 851.09,1326.35
  text ".Layer_Name" at 577,-858.49 h60

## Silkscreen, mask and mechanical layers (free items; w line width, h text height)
Top Overlay:
  lines w7: 1215,995 1150,995 1150,1255 1630,1255 1630,1045 ; 1670,1045 1670,1255 2175,1255 2175,995 1795,995 ; 1980,460 2183.86,460 2205,440 ; 1150,1295 1630,1295 1630,1555 1150,1555 1150,1295 ; 1670,1295 1670,1555 2175,1555 2175,1295 1670,1295
  lines w10: 325,325 325,1750 2275,1750 2275,325 325,325
  text "'.PRJ_Number'.PCB_Rev" at 400,200 h120
  text ".Layer_Name" at 577,-858.49 h60
Bottom Overlay:
  text ".Layer_Name" at 577,-858.49 h60
Top Paste:
  text ".Layer_Name" at 577,-858.49 h60
Bottom Paste:
  text ".Layer_Name" at 577,-858.49 h60
Top Solder:
  text ".Layer_Name" at 577,-858.49 h60
  text ".Layer_Name" at 577,-858.49 h60
Bottom Solder:
  text ".Layer_Name" at 577,-858.49 h60
Drill Guide:
  text ".Layer_Name" at 577,-858.49 h60
M1 Board Outline:
  the board outline again, w10
  text ".Layer_Name" at 577,-858.49 h60
M2 Board Dimensions:
  rectangle: 0,-275 125,-150
  rectangle: 125,-400 500,-275
  lines w7: 0,-275 1000,-275 ; 125,-400 125,-150 ; 250,-400 250,-150 ; 500,-400 500,-150 ; 750,-400 750,-150 ; 0,-400 1000,-400 1000,-150 0,-150 0,-400
  text ".Layer_Name" at 577,-858.49 h60
M3 3D STEP Top:
  text ".Layer_Name" at 577,-858.49 h60
M4 3D STEP Bottom:
  text ".Layer_Name" at 577,-858.49 h60
M5 Assembly Top:
  lines w10: -292,-930.17 6308,-930.17 ; -292,-726.83 6310,-726.83 ; -292,-523.5 -292,-1133.5 3713,-1133.5 6310,-1133.5 6310,-523.5 -291.5,-523.5 -291.5,-1133.5 1284,-1133.5 ; 2173,-1133.5 2173,-523.5 ; 3440,-726.83 3440,-523.5 ; 4280,-726.83 4280,-523.5 ; 4902,-1140 4902,-937.17
  text "COMPONENTS MARKED 'DNP' SHOULD NOT BE POPULATED." at 1153.5,-318.5 h60
  text "ASSEMBLY VARIANT:" at 1153,-434 h60
  text ".VariantName" at 2189,-434 h60
  text "PCB VIEWED FROM TOP SIDE" at -228.5,-655.67 h60
  text "BOARD #:" at 2248,-655.67 h60
  text ".PRJ_Number" at 2793.5,-655.67 h60
  text "REV:" at 3638,-655.67 h60
  text ".PCB_Rev" at 3929.5,-655.67 h60
  text "SVN REV:" at 4476,-655.67 h60
  text ".VersionControl_RevNumber" at 4982,-655.67 h60
  text "TID #:" at 2248,-859 h60
  text ".TID" at 2793.5,-859 h60
  text "PLOT NAME =" at -228.5,-1064.34 h60
  text ".plot_File_Name" at 577,-1064.34 h60
  text "GENERATED    :" at 2250,-1064.34 h60
  text ".Print_Date" at 3119.5,-1064.34 h60
  text ".Print_Time" at 3848.5,-1064.34 h60
  text "TEXAS INSTRUMENTS" at 5113,-1064.34 h60
M6 Assembly Bottom:
  lines w10: -292.5,-727.33 6309.5,-727.33 ; -290.5,-930.67 6309.5,-930.67 ; 1115.5,-1140.5 1115.5,-937.67 ; 1737.5,-727.33 1737.5,-524 ; 2577.5,-727.33 2577.5,-524 ; 3844.5,-1134 3844.5,-524 ; 4733.5,-1134 6309,-1134 6309,-524 -292.5,-524 -292.5,-1134 2304.5,-1134 6309.5,-1134 6309.5,-524
  text "COMPONENTS MARKED 'DNP' SHOULD NOT BE POPULATED." at 6102,-318 h60
  text ".VariantName" at 5058,-434 h60
  text "ASSEMBLY VARIANT:" at 6097,-434 h60
  text ".VersionControl_RevNumber" at 1035.5,-656.17 h60
  text "SVN REV:" at 1541.5,-656.17 h60
  text ".PCB_Rev" at 2088,-656.17 h60
  text "REV:" at 2379.5,-656.17 h60
  text ".PRJ_Number" at 3224,-656.17 h60
  text "BOARD #:" at 3769.5,-656.17 h60
  text "PCB VIEWED FROM BOTTOM SIDE" at 6246,-656.17 h60
  text ".TID" at 3224,-859.5 h60
  text "TID #:" at 3769.5,-859.5 h60
  text "TEXAS INSTRUMENTS" at 904.5,-1064.84 h60
  text ".Print_Time" at 2169,-1064.84 h60
  text ".Print_Date" at 2898,-1064.84 h60
  text "GENERATED    :" at 3767.5,-1064.84 h60
  text ".plot_File_Name" at 5440.5,-1064.84 h60
  text "PLOT NAME =" at 6246,-1064.84 h60
M9 Title Sheet:
  drawing of 57 lines, arcs and shapes, not listed
  text "1" at 739.84,8036.5 h70
  text "2" at 3235.5,8036.5 h70
  text "3" at 5724.84,8036.5 h70
  text "4" at 8231.51,8036.5 h70
  text "5" at 10730.5,8036.5 h70
  text "6" at 13235.5,8036.5 h70
  text "A" at -416.5,6893.5 h70
  text "A" at 14383.5,6893.5 h70
  text "B" at -416.5,4513.5 h70
  text "B" at 14383.5,4513.5 h70
  text "C" at -416.5,2138.5 h70
  text "C" at 14383.5,2138.5 h70
  text "PROJECT TITLE:" at 11343.5,277.5 h45
  text ".PRJ_Title" at 11393.5,144.17 h70
  text "DESIGNED FOR:" at 11343.5,-23.5 h45
  text ".PRJ_Customer" at 11393.5,-163.5 h70
  text "D" at -416.5,-231.5 h70
  text "D" at 14383.5,-231.5 h70
  text "FILE NAME:" at 11343.5,-323.5 h45
  text ".PCB_File_Name_No_Path" at 11393.5,-443.5 h70
  text "Texas Instruments (TI) and/or its licensors do not warrant the accuracy or completeness of this specification" at 6374,-605.34 h45
  text "ENGINEER:" at 11343.5,-613.5 h45
  text "LAYOUT BY:" at 12848.5,-613.5 h45
  text "or any information contained therein. TI and/or its licensors do not warrant that this design will meet" at 6329.01,-718 h45
  text ".PRJ_Engineer" at 11393.5,-768.49 h70
  text ".PCB_Layout" at 12899,-768.49 h70
  text "the specifications, will be suitable for your application or fit for any particular purpose, or will operate in" at 6329.01,-830.67 h45
  text ".Layer_Name" at 577,-858.49 h60
  text "ALTIUM DESIGNER VERSION:" at 12848.5,-923.5 h45
  text "an implementation. TI and/or its licensors do not warrant that the design is production worthy. You should" at 6329.01,-943.33 h45
  text "completely validate and test your design implementation to confirm the system functionality for your application." at 6374,-1056 h45
  text ".print_Scale" at 11393.5,-1056.83 h70
  text ".Application_BuildNumber" at 12899,-1056.83 h70
  text "1" at 739.84,-1263.5 h70
  text "2" at 3235.5,-1263.5 h70
  text "3" at 5724.84,-1263.5 h70
  text "4" at 8231.51,-1263.5 h70
  text "5" at 10730.5,-1263.5 h70
  text "6" at 13235.5,-1263.5 h70
M10 Fab Notes:
  drawing of 189 lines, arcs and shapes, not listed
  text "DESIGN INFORMATION" at 12382.02,6356.17 h60
  text "MIN. TRACK WIDTH:" at 11737.46,6224.05 h60
  text "8" at 12833.7,6224.05 h60
  text "MIL" at 12988.46,6224.05 h60
  text "7.874" at 12667.32,6102.36 h60
  text "MIN. CLEARANCE:" at 11737.46,6099.92 h60
  text "MIL" at 12988.46,6099.92 h60
  text "MIN. VIA PAD SIZE:" at 11737.46,5975.8 h60
  text "24" at 12803.71,5975.8 h60
  text "MIL" at 12988.46,5975.8 h60
  text "0.05mm (2MIL)" at 12432.46,5845.9 h60
  text "MINIMUM ANNULAR RING" at 11408.23,5837.67 h60
  text "EXTERNAL" at 13140.46,5837.67 h60
  text "PER" at 11608.23,5727.55 h60
  text "IPC-D-275 CLASS 2 LEVEL C" at 11828.23,5727.54 h60
  text "MIL, HOLES" at 13316.46,5627.07 h60
  text "+/-" at 12924,5618.48 h60
  text "+/-" at 13778,5618.48 h60
  text "REGISTRATION TOLERANCES:" at 11408.23,5617.42 h60
  text "METAL" at 12608,5617.42 h60
  text "5" at 13184.2,5617.42 h60
  text "3" at 14017.2,5617.42 h60
  text "MIL" at 14133.46,5617.42 h60
  text "HOLE SIZE TOLERANCE (UNLESS OTHERWISE SPECIFIED):" at 11408.23,5519.1 h60
  text "+/-" at 13778,5516.23 h60
  text "3" at 14017.2,5515.17 h60
  text "MIL" at 14133.46,5515.17 h60
  text "MATERIAL:" at 11333.46,5377.52 h60
  text "FR-4 High Tg" at 12319.9,5249 h60
  text "X" at 12175.46,5241.01 h60
  text "FR-408" at 11754.46,5236.49 h60
  text "OTHER" at 13242.46,5236.49 h60
  text "62 MIL (1.6mm) +/-10%" at 12074.56,5093.46 h60
  text "X" at 11954.46,5091.01 h60
  text "THICKNESS:" at 11408.23,5085.24 h60
  text "OTHER" at 13359.46,5085.24 h60
  text "TOLERANCE:" at 11408.23,4946.92 h60
  text "X" at 12256.46,4946.92 h60
  text "ANSI IPC-6012 TYPE 3 CLASS 2" at 12434.48,4946.92 h60
  text "OTHER +/-" at 12434.46,4802.73 h60
  text "BOW & TWIST:" at 11408.23,4657.54 h60
  text "X" at 12256.46,4657.54 h60
  text "ANSI IPC-6012 TYPE 3 CLASS 2" at 12434.48,4657.54 h60
  text "OTHER +/-" at 12434.46,4510.85 h60
  text "DRILLING:" at 11333.46,4380.23 h60
  text "NC_DRILL FILES" at 13094.46,4275.04 h60
  text "REFERENCE:" at 11408.23,4271.1 h60
  text "X" at 12065.46,4271.01 h60
  text "AS SHOWN" at 12243.46,4271.1 h60
  text "X" at 12966.46,4271.1 h60
  text "OTHER" at 13392.46,4128.85 h60
  text "PTH COPPER THICKNESS:" at 11407.91,4125.32 h60
  text "X" at 12547.14,4125.32 h60
  text "20-30 um" at 12675.14,4125.32 h60
  text "BOARD FINISH:" at 11333.46,3977.73 h60
  text "SILKSCREEN:" at 11488.68,3867.6 h60
  text "X" at 12446.46,3867.6 h60
  text "TOP" at 12563.46,3867.6 h60
  text "X" at 12956.46,3867.6 h60
  text "BOTTOM" at 13074.46,3867.6 h60
  text "SILKSCREEN COLOR:" at 11488.68,3712.41 h60
  text "X" at 12445.46,3712.41 h60
  text "WHITE" at 12563.46,3712.41 h60
  text "OTHER" at 13074.46,3712.41 h60
  text "X" at 12576.46,3568.96 h60
  text "GREEN" at 12694.46,3568.96 h60
  text "OTHER" at 13312.46,3568.96 h60
  text "SOLDER RESIST COLOR:" at 11488.68,3562.1 h60
  text "X" at 12576.46,3414.71 h60
  text "MATTE" at 12694.46,3414.71 h60
  text "SEMI-GLOSS" at 13312,3414.07 h60
  text "IMMERSION GOLD (ENIG)" at 12394.46,3241.94 h60
  text "ENEPIG" at 13732,3234.72 h60
  text "SURFACE FINISH:" at 11333.46,3233.72 h60
  text "X" at 12216.46,3233.72 h60
  text "IMM. TIN/SILVER OR EQUIV" at 11663,3096.4 h60
  text "OTHER" at 13094.46,3092.47 h60
  text "ARRAY/PANEL:" at 11333.46,2937.09 h60
  text "CUT AND TRIM PER M1 BOARD OUTLINE" at 12394.46,2928.87 h60
  text "N.C. ROUTE" at 12394.46,2792.9 h60
  text "X" at 13082.46,2792.9 h60
  text "V. SCORE" at 13260.46,2792.9 h60
  text "CERTIFICATION:" at 11333.46,2663.77 h60
  text "MATERIALS AND WORKMANSHIP FOR ALL PCBS" at 12058.46,2663.77 h60
  text "TO MEET OR EXCEED THE REQUIREMENTS OF:" at 12058.46,2569.71 h60
  text "X" at 11695.97,2441.08 h60
  text "ANSI IPC-A-600F CLASS ->" at 11823.96,2441.08 h60
  text "X" at 13471.97,2441.08 h60
  text "2" at 13581.96,2441.08 h60
  text "1" at 13266.96,2439.58 h60
  text "3" at 13935.96,2439.58 h60
  text "X" at 12507.97,2293.39 h60
  text "RoHS" at 12635.96,2293.39 h60
  text "OTHER" at 13280.36,2293.39 h60
  text "PER ORDER" at 13677.42,2293.39 h60
  text "ALL BOARDS MUST MEET OR EXCEED UL94-V0 REQUIREMENTS." at 11361,2139.57 h60
  text "PCB MUST BEAR THE UL94V-0 UL REGISTERED MATERIAL ID NUMBER" at 11361,2023.5 h60
  text "ADDITIONAL REQUIREMENTS:" at 11333.46,1854.08 h60
  text "MICROSECTION:" at 11408.23,1746.95 h60
  text "YES" at 12313.96,1746.95 h60
  text "REQUIRED" at 13175.46,1602.62 h60
  text "BARE BOARD ELEC. TEST:" at 11408.23,1599.76 h60
  text "NONE" at 12713.96,1599.76 h60
  text "X" at 13057.46,1599.76 h60
  text "PER ORDER" at 13767.46,1599.76 h60
  text "XX MIL VIAS REQUIRE NON-CONDUCTIVE FILL AND PLANARIZE" at 11576.38,1394.82 h59
  text "XX MIL VIAS REQUIRE CONDUCTIVE FILL AND PLANARIZE" at 11584.38,1290.84 h60
  text "OUTER XX MIL TRACES REQUIRE 50 OHM SINGLE-ENDED IMPEDANCE" at 11583.39,1127.46 h58
  text "LAYER 2 & 3 (INNER LAYERS) XX MIL WIDE, XX MIL SPACE / TRACES REQUIRE 100 OHM DIFFERENTIAL IMPEDANCE" at 11575.39,891.74 h60
  text ".Layer_Name" at 577,-858.49 h60
M11 Gerber Information:
  lines w10: -292,-930.17 6308,-930.17 ; -292,-726.83 6310,-726.83 ; -292,-523.5 -292,-1133.5 3713,-1133.5 6310,-1133.5 6310,-523.5 -291.5,-523.5 -291.5,-1133.5 1284,-1133.5 ; 2173,-1133.5 2173,-523.5 ; 3440,-726.83 3440,-523.5 ; 4280,-726.83 4280,-523.5 ; 4902,-1140 4902,-937.17
  text "ALL ARTWORK VIEWED FROM TOP SIDE" at -228.5,-655.67 h60
  text "BOARD #:" at 2248,-655.67 h60
  text ".PRJ_Number" at 2793.5,-655.67 h60
  text "REV:" at 3638,-655.67 h60
  text ".PCB_Rev" at 3929.5,-655.67 h60
  text "SVN REV:" at 4476,-655.67 h60
  text ".VersionControl_RevNumber" at 4982,-655.67 h60
  text "LAYER NAME =" at -228.5,-858.49 h60
  text "TID #:" at 2248,-859 h60
  text ".TID" at 2793.5,-859 h60
  text "PLOT NAME =" at -228.5,-1064.34 h60
  text ".plot_File_Name" at 577,-1064.34 h60
  text "GENERATED    :" at 2250,-1064.34 h60
  text ".Print_Date" at 3119.5,-1064.34 h60
  text ".Print_Time" at 3848.5,-1064.34 h60
  text "TEXAS INSTRUMENTS" at 5113,-1064.34 h60
M12 Stackup:
  drawing of 191 lines, arcs and shapes, not listed
  text "Layer" at 9821.59,7874.94 h60
  text "Name" at 10231.51,7874.94 h60
  text "Material" at 11161.25,7874.94 h60
  text "Thickness" at 12021.02,7874.94 h60
  text "Constant" at 12670.85,7874.94 h60
  text "Board Layer Stack" at 13240.71,7874.94 h60
  text "Top Overlay" at 10231.51,7754.94 h60
  text "Top Solder" at 10231.51,7634.94 h60
  text "Solder Resist" at 11161.25,7634.94 h60
  text "0.40mil" at 12021.02,7634.94 h60
  text "3.5" at 12670.85,7634.94 h60
  text "1" at 9821.59,7514.94 h60
  text "Top Layer" at 10231.51,7514.94 h60
  text "1.40mil" at 12021.02,7514.94 h60
  text "Dielectric1" at 10231.51,7394.94 h60
  text "FR-4 High Tg" at 11161.25,7394.94 h60
  text "59.20mil" at 12021.02,7394.94 h60
  text "4.8" at 12670.85,7394.94 h60
  text "2" at 9821.59,7274.94 h60
  text "Bottom Layer" at 10231.51,7274.94 h60
  text "1.40mil" at 12021.02,7274.94 h60
  text "Bottom Solder" at 10231.51,7154.94 h60
  text "Solder Resist" at 11161.25,7154.94 h60
  text "0.40mil" at 12021.02,7154.94 h60
  text "3.5" at 12670.85,7154.94 h60
  text "Bottom Overlay" at 10231.51,7034.94 h60
  text ".Layer_Name" at 577,-858.49 h60
M13 Component Bodies Top:
  text ".Layer_Name" at 577,-858.49 h60
M14 Component Bodies Bottom:
  text ".Layer_Name" at 577,-858.49 h60
M15 Courtyards Top:
  text ".Layer_Name" at 577,-858.49 h60
M16 Courtyards Bottom:
  text ".Layer_Name" at 577,-858.49 h60
Drill Drawing:
  text ".Layer_Name" at 577,-858.49 h60
M17 Embedded Cavity:
  text ".Layer_Name" at 577,-858.49 h60
M18 Embedded Assembly:
  text ".Layer_Name" at 577,-858.49 h60
M19 Embedded Keepout:
  text ".Layer_Name" at 577,-858.49 h60

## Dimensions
0,-400 to 1000,-400 on M2 Board Dimensions
0,2075 to 2600,0 on M2 Board Dimensions
2600,0 to 0,2075 on M2 Board Dimensions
